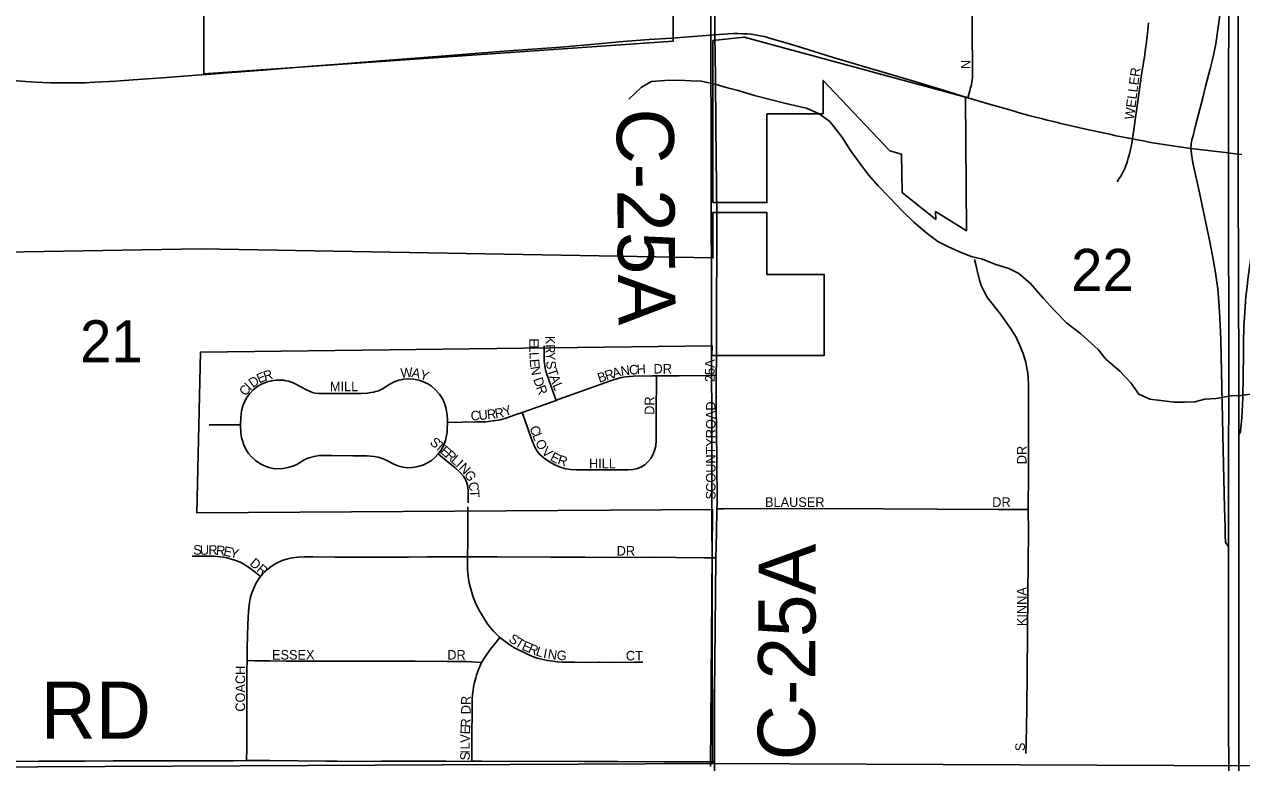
# Model space of a CAD drawing. Extents: x 0 to 680, y 0 to 440.
# Drawn here: x 477.97 to 499.3, y 223.99 to 236.91 of the extents above; entities that cross this region are included whole.
import ezdxf

# ---------------------------------------------------------------- set-up
doc = ezdxf.new("R2010")
doc.units = 0
for name, color, linetype in [('GM_X_City_Street', 7, 'Continuous'), ('GM_X_City_Street_Text', 7, 'Continuous'), ('GM_X_Corporation', 7, 'Continuous'), ('GM_X_County_Road', 7, 'Continuous'), ('GM_X_County_Road_Text', 7, 'Continuous'), ('GM_X_Interchange_Ramps', 7, 'Continuous'), ('GM_X_Interstate_Route', 7, 'Continuous'), ('GM_X_Minor_River', 7, 'Continuous'), ('GM_X_Section', 7, 'Continuous'), ('GM_X_Section_Text', 7, 'Continuous'), ('GM_X_State_Route', 7, 'Continuous'), ('GM_X_Township_Road', 7, 'Continuous'), ('GM_X_Township_Road_Text', 7, 'Continuous'), ('GM_X_Township_Subdivision', 7, 'Continuous'), ('GM_X_Township_Subdivision_Text', 7, 'Continuous')]:
    doc.layers.add(name, color=color, linetype=linetype)

msp = doc.modelspace()

# ---------------------------------------------------------------- linework, layer by layer
at = {"layer": 'GM_X_City_Street'}
for points in [[(490.07, 236.729), (490.056, 238.186), (490.049, 238.92), (490.046, 239.367), (490.045, 239.582)], [(494.5, 235.627), (494.534, 235.751), (494.547, 235.799), (494.562, 235.856), (494.57, 235.9), (494.576, 235.941), (494.579, 235.973), (494.582, 236.011), (494.583, 236.071), (494.583, 236.166), (494.573, 236.756), (494.572, 237.556), (494.572, 238.422), (494.569, 239.255)], [(497.385, 234.905), (497.466, 235.487), (497.506, 235.78), (497.544, 236.036), (497.58, 236.271), (497.598, 236.385), (497.612, 236.482), (497.628, 236.603), (497.641, 236.71), (497.651, 236.813), (497.662, 236.937)], [(497.113, 234.157), (497.145, 234.205), (497.166, 234.238), (497.188, 234.272), (497.203, 234.298), (497.22, 234.33), (497.236, 234.363), (497.253, 234.403), (497.268, 234.441), (497.282, 234.482), (497.295, 234.521), (497.31, 234.569), (497.324, 234.621), (497.343, 234.695), (497.359, 234.767), (497.372, 234.835), (497.385, 234.905)], [(490.105, 233.392), (490.105, 233.473), (490.104, 233.558)], [(495.557, 228.417), (495.561, 229.067), (495.562, 229.614), (495.562, 230.573), (495.562, 230.631), (495.552, 230.806), (495.515, 230.993), (495.471, 231.149), (495.423, 231.263), (495.343, 231.435), (495.252, 231.579), (495.091, 231.813), (494.92, 232.029), (494.846, 232.123), (494.783, 232.233), (494.732, 232.342), (494.701, 232.431), (494.662, 232.603), (494.637, 232.707), (494.616, 232.794)], [(487.286, 230.329), (487.235, 230.473), (487.117, 230.804), (487.106, 230.843), (487.096, 230.889), (487.088, 230.937), (487.081, 231.008), (487.076, 231.15), (487.076, 231.282)], [(490.093, 230.768), (490.095, 231.052)], [(486.695, 230.117), (486.739, 229.99), (486.849, 229.669), (486.917, 229.508), (486.955, 229.441), (487.003, 229.382), (487.076, 229.316), (487.157, 229.259), (487.263, 229.203), (487.374, 229.156), (487.458, 229.131), (487.544, 229.117), (487.642, 229.113), (487.993, 229.112), (488.551, 229.112), (488.638, 229.12), (488.713, 229.138), (488.784, 229.166), (488.84, 229.201), (488.896, 229.252), (488.944, 229.312), (488.982, 229.378), (489.01, 229.45), (489.032, 229.535), (489.041, 229.621), (489.042, 230.257), (489.044, 230.585), (489.045, 230.761)], [(487.286, 230.329), (487.322, 230.342), (488.239, 230.67), (488.406, 230.723), (488.503, 230.742), (488.644, 230.754), (488.972, 230.761), (489.045, 230.761)], [(489.045, 230.761), (489.443, 230.761), (489.924, 230.766), (490.093, 230.768)], [(490.106, 228.52), (490.105, 229.298), (490.09, 230.238), (490.093, 230.768)], [(485.384, 229.941), (485.384, 229.989), (485.378, 230.07), (485.374, 230.105), (485.365, 230.146), (485.361, 230.167), (485.353, 230.204), (485.342, 230.241), (485.324, 230.296), (485.302, 230.342), (485.281, 230.383), (485.243, 230.436), (485.164, 230.527), (485.107, 230.578), (485.053, 230.615), (484.963, 230.656), (484.88, 230.684), (484.784, 230.702), (484.707, 230.706), (484.62, 230.699), (484.575, 230.691), (484.534, 230.681), (484.452, 230.652), (484.374, 230.611), (484.245, 230.529), (484.175, 230.498), (484.13, 230.484), (484.091, 230.474), (484.043, 230.464), (483.983, 230.456), (483.874, 230.451), (483.567, 230.451), (483.259, 230.447), (483.13, 230.449), (483.065, 230.456), (483.023, 230.465), (482.991, 230.477), (482.902, 230.518), (482.738, 230.608), (482.717, 230.618), (482.669, 230.639), (482.648, 230.646), (482.597, 230.663), (482.556, 230.673), (482.512, 230.68), (482.453, 230.685), (482.378, 230.682), (482.302, 230.673), (482.228, 230.653), (482.127, 230.612), (482.06, 230.575), (481.983, 230.512), (481.922, 230.45), (481.897, 230.422), (481.876, 230.389), (481.828, 230.303), (481.799, 230.232), (481.778, 230.147), (481.762, 230.028), (481.758, 229.902)], [(486.695, 230.117), (487.286, 230.329)], [(485.384, 229.941), (485.89, 229.951), (486.056, 229.956), (486.192, 229.969), (486.311, 229.988), (486.426, 230.022), (486.57, 230.073), (486.695, 230.117)], [(481.213, 229.902), (481.385, 229.902), (481.639, 229.902), (481.758, 229.902)], [(481.758, 229.902), (481.757, 229.875), (481.765, 229.766), (481.772, 229.709), (481.784, 229.658), (481.798, 229.606), (481.816, 229.553), (481.847, 229.484), (481.871, 229.443), (481.9, 229.401), (481.951, 229.343), (482.023, 229.277), (482.095, 229.226), (482.182, 229.181), (482.254, 229.154), (482.329, 229.138), (482.416, 229.132), (482.504, 229.137), (482.59, 229.151), (482.674, 229.176), (482.743, 229.208), (482.884, 229.293), (482.954, 229.323), (483.049, 229.349), (483.136, 229.361), (483.365, 229.364), (483.727, 229.359), (483.978, 229.356), (484.098, 229.349), (484.173, 229.335), (484.256, 229.307), (484.335, 229.269), (484.442, 229.213), (484.533, 229.177), (484.608, 229.158), (484.684, 229.15), (484.771, 229.154), (484.868, 229.17), (484.952, 229.195), (485.022, 229.227), (485.096, 229.273), (485.164, 229.329), (485.222, 229.391)], [(485.222, 229.391), (485.224, 229.393), (485.269, 229.454), (485.302, 229.512), (485.333, 229.582), (485.35, 229.632), (485.357, 229.655), (485.363, 229.682), (485.374, 229.741), (485.378, 229.771), (485.382, 229.823), (485.384, 229.941)], [(485.746, 228.537), (485.746, 228.733), (485.74, 228.82), (485.724, 228.884), (485.698, 228.944), (485.658, 229.008), (485.608, 229.066), (485.519, 229.147), (485.3, 229.327), (485.222, 229.391)], [(490.104, 228.43), (490.222, 228.431), (491.412, 228.434), (493.022, 228.43), (493.967, 228.425), (495.037, 228.42), (495.438, 228.418), (495.557, 228.417)], [(495.516, 224.146), (495.519, 224.32), (495.533, 224.931), (495.539, 225.569), (495.543, 226.225), (495.552, 226.964), (495.559, 228.026), (495.557, 228.417)], [(489.935, 216.438), (489.935, 216.438), (489.948, 217.062), (489.958, 217.746), (489.978, 218.906), (489.99, 219.727), (490.003, 220.472), (490.013, 221.304), (490.029, 222.212), (490.05, 223.274), (490.063, 224.001)]]:
    msp.add_lwpolyline(points, dxfattribs=at)
at = {"layer": 'GM_X_Corporation'}
msp.add_lwpolyline([(489.993, 223.916), (490.028, 228.417), (480.996, 228.36), (481.058, 231.171), (490.018, 231.285), (490.014, 231.113), (491.984, 231.115), (491.982, 232.533), (490.981, 232.533), (490.98, 233.618), (490.033, 233.617), (490.033, 232.823), (481.065, 232.983), (474.871, 232.875), (474.871, 236.22), (473.725, 236.49), (472.735, 236.905), (472.245, 237.111), (472.245, 241.651), (481.118, 241.691), (481.055, 250.48)], dxfattribs=at)
for points in [[(481.118, 241.691), (481.118, 236.046), (489.339, 236.618), (489.339, 237.172), (490.014, 237.16), (489.995, 239.503), (489.988, 239.503), (488.871, 239.486), (488.876, 240.02), (489.982, 240.037), (489.974, 240.431), (488.863, 240.392), (488.848, 242.067), (488.839, 242.461), (487.667, 242.441), (487.676, 241.828), (484.131, 241.754)], [(490.033, 236.632), (490.033, 233.791), (490.981, 233.791), (490.979, 235.345), (491.967, 235.346), (491.966, 235.93), (493.135, 234.7), (493.338, 234.64), (493.347, 233.969), (493.937, 233.498), (493.933, 233.633), (494.473, 233.299), (494.461, 235.639), (490.58, 236.685)]]:
    msp.add_lwpolyline(points, close=True, dxfattribs=at)
at = {"layer": 'GM_X_County_Road'}
for points in [[(490.104, 233.558), (490.085, 235.118), (490.081, 235.986), (490.07, 236.729)], [(490.103, 233.025), (490.104, 233.195), (490.105, 233.391), (490.105, 233.392)], [(490.095, 231.387), (490.097, 231.934), (490.103, 233.021), (490.103, 233.025)], [(490.095, 231.052), (490.098, 231.228), (490.095, 231.387)], [(490.085, 227.574), (490.097, 228.006), (490.104, 228.43)], [(490.104, 228.43), (490.106, 228.52)], [(490.063, 224.001), (490.063, 225.229), (490.074, 226.342), (490.085, 227.574)]]:
    msp.add_lwpolyline(points, dxfattribs=at)
at = {"layer": 'GM_X_Interchange_Ramps'}
for points in [[(499.069, 239.688), (499.034, 239.608), (499.013, 239.56), (499.007, 239.514), (499.005, 239.374), (499.004, 239.346), (498.988, 238.283), (498.982, 237.965), (498.974, 237.801), (498.951, 237.463), (498.917, 237.114), (498.881, 236.82), (498.841, 236.572), (498.796, 236.346), (498.745, 236.133), (498.663, 235.826), (498.618, 235.628), (498.484, 235.117), (498.444, 234.963), (498.425, 234.89), (498.413, 234.823), (498.406, 234.74)], [(498.406, 234.74), (498.422, 234.604), (498.441, 234.49), (498.55, 233.993), (498.739, 233.103), (498.81, 232.738), (498.845, 232.521), (498.876, 232.282), (498.898, 232.053), (498.915, 231.78), (498.93, 231.385), (498.97, 229.464), (498.995, 228.45), (499.004, 228.115), (499.007, 227.939), (499.011, 227.876), (499.013, 227.851), (499.026, 227.821), (499.045, 227.792), (499.066, 227.763)], [(499.245, 229.732), (499.265, 229.755), (499.273, 229.776), (499.277, 229.801), (499.288, 229.904), (499.299, 230.021), (499.314, 230.372), (499.325, 231.139), (499.328, 231.347), (499.336, 231.61), (499.349, 231.873), (499.371, 232.146), (499.39, 232.323), (499.41, 232.494), (499.456, 232.82), (499.561, 233.47), (499.609, 233.77), (499.662, 234.115), (499.726, 234.469), (499.742, 234.589)]]:
    msp.add_lwpolyline(points, dxfattribs=at)
at = {"layer": 'GM_X_Interstate_Route'}
for points in [[(499.074, 221.303), (499.067, 225.241), (499.066, 227.763), (499.065, 229.04), (499.069, 230.749), (499.063, 234.252), (499.064, 234.66), (499.068, 235.598), (499.07, 237.416), (499.069, 239.688), (499.068, 241.014), (499.057, 245.417), (499.021, 246.364)], [(499.251, 215.048), (499.251, 215.074), (499.251, 217.418), (499.248, 220.255), (499.248, 224.759), (499.245, 229.732), (499.245, 230.699), (499.235, 234.233), (499.236, 234.641), (499.237, 236.207), (499.231, 238.398), (499.236, 241.137), (499.239, 243.03), (499.243, 244.793), (499.238, 245.307), (499.227, 245.734), (499.207, 246.182), (499.197, 246.357)]]:
    msp.add_lwpolyline(points, dxfattribs=at)
at = {"layer": 'GM_X_Minor_River'}
for points in [[(491.672, 235.443), (491.465, 235.493), (491.285, 235.535), (491.058, 235.592), (490.765, 235.669), (490.479, 235.753), (490.266, 235.809), (490.073, 235.865), (489.826, 235.915), (489.652, 235.924), (489.439, 235.933), (489.191, 235.929), (488.957, 235.912), (488.782, 235.814), (488.559, 235.603)], [(499.545, 230.447), (499.284, 230.417), (499.11, 230.406), (498.849, 230.362), (498.648, 230.351), (498.474, 230.306), (498.293, 230.295), (498.113, 230.298), (497.926, 230.32), (497.686, 230.35), (497.493, 230.439), (497.355, 230.635), (497.164, 230.838), (496.919, 231.048), (496.781, 231.217), (496.477, 231.496), (496.225, 231.686), (496.014, 231.91), (495.816, 232.12), (495.598, 232.377), (495.393, 232.553), (495.22, 232.636), (494.974, 232.712), (494.754, 232.802), (494.555, 232.845), (494.342, 232.934), (494.162, 233.017), (493.976, 233.113), (493.784, 233.249), (493.553, 233.446), (493.354, 233.642), (493.13, 233.88), (492.925, 234.089), (492.76, 234.279), (492.603, 234.488), (492.445, 234.704), (492.294, 234.94), (492.083, 235.211), (491.898, 235.347), (491.672, 235.443)]]:
    msp.add_lwpolyline(points, dxfattribs=at)
at = {"layer": 'GM_X_Section'}
msp.add_lwpolyline([(472.268, 225.115), (472.319, 241.773), (489.987, 242.13), (490.027, 223.974), (473.467, 223.892)], dxfattribs=at)
msp.add_lwpolyline([(507.628, 241.733), (507.54, 223.893), (490.027, 223.974), (489.987, 242.13), (499.118, 242.119)], close=True, dxfattribs=at)
at = {"layer": 'GM_X_State_Route'}
for points in [[(489.315, 236.671), (489.613, 236.691), (489.842, 236.71)], [(489.842, 236.71), (490.07, 236.729)], [(490.07, 236.729), (490.295, 236.748), (490.397, 236.752), (490.479, 236.752), (490.559, 236.749), (490.634, 236.745), (490.701, 236.74), (490.772, 236.731), (490.831, 236.719), (490.895, 236.706), (490.93, 236.697)], [(490.93, 236.697), (490.974, 236.686), (491.085, 236.655), (491.229, 236.612), (491.413, 236.557), (491.619, 236.493), (491.899, 236.407), (492.139, 236.334), (492.377, 236.263), (492.656, 236.18), (492.977, 236.085), (493.569, 235.909), (494.169, 235.728), (494.5, 235.627)], [(481.162, 236.035), (481.532, 236.062), (482.074, 236.105), (483.008, 236.178), (483.48, 236.215), (484.29, 236.281), (485.272, 236.357), (486.379, 236.441), (487.37, 236.515), (488.031, 236.573), (488.384, 236.604), (488.917, 236.646), (489.315, 236.671)], [(477.074, 235.976), (478.169, 235.901), (478.43, 235.889), (478.666, 235.887), (478.804, 235.887), (478.924, 235.888), (479.039, 235.891), (479.207, 235.898), (479.343, 235.904), (479.576, 235.92), (479.877, 235.94), (480.387, 235.978), (480.913, 236.017), (480.986, 236.022)], [(480.986, 236.022), (481.162, 236.035)], [(494.5, 235.627), (494.899, 235.508), (495.127, 235.442), (495.27, 235.401), (495.419, 235.359), (495.57, 235.319), (495.687, 235.288), (495.79, 235.262), (495.889, 235.237), (495.999, 235.21), (496.044, 235.199)], [(496.044, 235.199), (496.129, 235.178), (496.255, 235.148), (496.438, 235.106), (496.617, 235.065), (496.816, 235.022), (497.007, 234.981), (497.092, 234.963)], [(497.092, 234.963), (497.159, 234.949), (497.29, 234.923), (497.385, 234.905), (497.436, 234.895), (497.568, 234.871), (497.704, 234.846), (497.815, 234.827), (498.011, 234.796), (498.406, 234.74), (498.602, 234.714), (498.858, 234.684), (499.064, 234.66), (499.095, 234.656), (499.236, 234.641), (499.299, 234.635)]]:
    msp.add_lwpolyline(points, dxfattribs=at)
at = {"layer": 'GM_X_Township_Road'}
for points in [[(474.934, 224.01), (476.17, 224.013), (476.576, 224.009), (477.416, 224.01), (477.668, 224.008), (478.226, 224.01), (478.599, 224.011), (479.026, 224.013), (479.53, 224.016), (480.066, 224.018), (480.548, 224.019), (481.565, 224.017), (481.638, 224.018), (481.862, 224.022)], [(481.862, 224.022), (482.272, 224.021), (483.256, 224.013), (483.453, 224.01), (483.902, 224.007), (484.23, 224.011), (484.394, 224.011), (484.709, 224.013), (485.046, 224.012), (485.353, 224.011), (485.583, 224.009), (485.809, 224.014)], [(485.809, 224.014), (485.986, 224.01), (487.779, 224.008)], [(487.779, 224.008), (487.911, 224.009), (488.37, 224.005), (489.179, 223.999), (489.617, 223.999), (490.063, 224.001)]]:
    msp.add_lwpolyline(points, dxfattribs=at)
at = {"layer": 'GM_X_Township_Subdivision'}
for points in [[(485.744, 228.465), (485.744, 228.238), (485.743, 227.877), (485.737, 227.592)], [(480.915, 227.6), (481.042, 227.599), (481.295, 227.6), (481.404, 227.592), (481.458, 227.584), (481.522, 227.571), (481.66, 227.533), (481.751, 227.497), (481.829, 227.456), (481.938, 227.382), (482.015, 227.321), (482.112, 227.245)], [(482.112, 227.245), (482.145, 227.286), (482.216, 227.356), (482.295, 227.418), (482.39, 227.476), (482.491, 227.524), (482.586, 227.557), (482.662, 227.574), (482.765, 227.585), (482.878, 227.59), (483.025, 227.588), (483.415, 227.585), (483.6, 227.586), (484.038, 227.583), (484.333, 227.585), (484.704, 227.584), (485.032, 227.587), (485.737, 227.592)], [(485.737, 227.592), (485.736, 227.528), (485.737, 227.428), (485.738, 227.373), (485.743, 227.296), (485.746, 227.258), (485.753, 227.201), (485.767, 227.137), (485.787, 227.048), (485.822, 226.923), (485.845, 226.853), (485.876, 226.783), (485.936, 226.659), (486.013, 226.528), (486.091, 226.407), (486.188, 226.29), (486.272, 226.206), (486.303, 226.176)], [(485.737, 227.592), (485.82, 227.592), (486.254, 227.587), (487.193, 227.586), (487.795, 227.582), (488.266, 227.579), (488.901, 227.582), (489.887, 227.575), (490.085, 227.574)], [(481.873, 225.773), (481.876, 225.996), (481.89, 226.41), (481.899, 226.63), (481.915, 226.789), (481.929, 226.862), (481.951, 226.942), (481.991, 227.043), (482.03, 227.124), (482.082, 227.207), (482.112, 227.245)], [(485.982, 225.741), (486.032, 225.822), (486.132, 225.965), (486.212, 226.067), (486.303, 226.176)], [(486.303, 226.176), (486.371, 226.122), (486.461, 226.06), (486.546, 226.005), (486.579, 225.987), (486.706, 225.925), (486.799, 225.879), (486.875, 225.846), (486.955, 225.815), (487.059, 225.79), (487.139, 225.775), (487.231, 225.762), (487.31, 225.752), (487.393, 225.748), (487.467, 225.747), (487.611, 225.746), (487.884, 225.741), (488.037, 225.745), (488.048, 225.748), (488.222, 225.742), (488.671, 225.744), (488.808, 225.744)], [(481.862, 224.022), (481.868, 224.233), (481.87, 225.602), (481.873, 225.773)], [(481.873, 225.773), (482.005, 225.771), (482.279, 225.766), (482.564, 225.765), (484.152, 225.762), (484.821, 225.761), (485.38, 225.757), (485.715, 225.757), (485.982, 225.741)], [(485.809, 224.014), (485.81, 224.121), (485.813, 224.461), (485.815, 224.887), (485.816, 225.007), (485.817, 225.084), (485.825, 225.183), (485.833, 225.251), (485.841, 225.315), (485.856, 225.392), (485.88, 225.469), (485.895, 225.52), (485.918, 225.587), (485.982, 225.741)]]:
    msp.add_lwpolyline(points, dxfattribs=at)

# ---------------------------------------------------------------- texts
at = {"layer": 'GM_X_City_Street_Text'}
for s, height, rotation, p in [('N', 0.167, 90, (494.544, 236.128)), ('WELLER', 0.1669, 82.7469, (497.408, 235.236)), ('E', 0.167, 270.0547, (486.817, 231.414)), ('K', 0.167, 270.2405, (487.101, 231.458)), ('L', 0.167, 270.502, (486.817, 231.295)), ('L', 0.167, 272.6217, (486.819, 231.171)), ('R', 0.167, 270.2429, (487.102, 231.311)), ('Y', 0.167, 273.0711, (487.103, 231.17)), ('E', 0.167, 274.1816, (486.824, 231.048)), ('N', 0.167, 280.3218, (486.835, 230.912)), ('S', 0.167, 275.833, (487.111, 231.014)), ('N', 0.167, 8.1796, (488.429, 230.755)), ('C', 0.167, 5.1307, (488.572, 230.775)), ('H', 0.167, 3.5204, (488.703, 230.787)), ('DR', 0.1669, 0, (488.994, 230.799)), ('25A', 0.1669, 90, (490.064, 230.65)), ('D', 0.167, 35.8426, (481.975, 230.542)), ('E', 0.167, 23.6435, (482.086, 230.623)), ('R', 0.167, 16.8528, (482.188, 230.668)), ('W', 0.167, 4.0557, (484.568, 230.725)), ('A', 0.167, 347.9785, (484.746, 230.74)), ('Y', 0.167, 341.9797, (484.885, 230.71)), ('D', 0.167, 289.5067, (486.883, 230.698)), ('T', 0.167, 287.5986, (487.131, 230.861)), ('A', 0.167, 289.9884, (487.169, 230.742)), ('B', 0.167, 17.8205, (488.043, 230.636)), ('R', 0.167, 17.7974, (488.169, 230.676)), ('A', 0.167, 15.6692, (488.294, 230.716)), ('C', 0.167, 53.3049, (481.853, 230.393)), ('I', 0.167, 44.9072, (481.928, 230.494)), ('MILL', 0.1669, 0, (483.325, 230.49)), ('R', 0.167, 290.0853, (486.933, 230.558)), ('L', 0.167, 291.811, (487.221, 230.598)), ('DR', 0.1669, 90, (489.006, 230.077)), ('ROAD', 0.1669, 90, (490.079, 229.666)), ('C', 0.167, 2.1615, (485.794, 229.977)), ('U', 0.167, 5.7664, (485.937, 229.982)), ('R', 0.167, 6.4352, (486.086, 229.997)), ('R', 0.167, 9.1964, (486.226, 230.013)), ('Y', 0.167, 21.0649, (486.392, 230.044)), ('C', 0.167, 288.9496, (486.821, 229.852)), ('S', 0.167, 319.7187, (485.063, 229.573)), ('L', 0.167, 291.7162, (486.867, 229.719)), ('COUNTY', 0.1669, 90, (490.079, 228.726)), ('T', 0.167, 319.6802, (485.153, 229.497)), ('E', 0.167, 319.7075, (485.243, 229.42)), ('R', 0.167, 319.7095, (485.332, 229.345)), ('O', 0.167, 296.4188, (486.916, 229.596)), ('V', 0.167, 317.6304, (487.022, 229.411)), ('DR', 0.1669, 90, (495.527, 229.211)), ('L', 0.167, 319.6898, (485.433, 229.259)), ('I', 0.167, 316.5148, (485.521, 229.185)), ('N', 0.167, 314.9227, (485.573, 229.135)), ('E', 0.167, 332.3455, (487.169, 229.285)), ('R', 0.167, 341.8909, (487.301, 229.219)), ('HILL', 0.1669, 0, (487.863, 229.139)), ('G', 0.167, 301.1737, (485.67, 229.039)), ('C', 0.167, 280.281, (485.75, 228.886)), ('T', 0.167, 272.7328, (485.773, 228.761)), ('S', 0.167, 90, (490.079, 228.594)), ('BLAUSER', 0.1669, 0, (490.947, 228.464)), ('DR', 0.1669, 0, (494.927, 228.464)), ('KINNA', 0.1669, 90, (495.527, 226.376)), ('S', 0.167, 90, (495.498, 224.188))]:
    msp.add_text(s, height=height, rotation=rotation, dxfattribs=at).set_placement(p)
at = {"layer": 'GM_X_County_Road_Text'}
for rotation, p in [(270.548, (488.345, 235.435)), (89.748, (491.82, 224.025))]:
    msp.add_text('C-25A', height=1.0014, rotation=rotation, dxfattribs=at).set_placement(p)
at = {"layer": 'GM_X_Section_Text'}
for s, p in [('22', (496.308, 232.243)), ('21', (478.948, 230.994))]:
    msp.add_text(s, height=0.7377, rotation=0, dxfattribs=at).set_placement(p)
at = {"layer": 'GM_X_Township_Road_Text'}
msp.add_text('RD', height=1.0014, rotation=0, dxfattribs=at).set_placement((478.258, 224.405))
at = {"layer": 'GM_X_Township_Subdivision_Text'}
for s, height, rotation, p in [('S', 0.167, 359.8907, (480.931, 227.627)), ('U', 0.167, 359.8907, (481.048, 227.626)), ('R', 0.167, 359.8786, (481.195, 227.626)), ('R', 0.167, 354.038, (481.323, 227.626)), ('E', 0.167, 348.9793, (481.45, 227.613)), ('Y', 0.167, 345.6881, (481.563, 227.591)), ('DR', 0.1669, 0, (488.348, 227.612)), ('DR', 0.1669, 319.0784, (481.907, 227.457)), ('S', 0.167, 323.2175, (486.443, 226.122)), ('T', 0.167, 329.0958, (486.552, 226.041)), ('E', 0.167, 336.1503, (486.673, 225.971)), ('R', 0.167, 337.7323, (486.785, 225.921)), ('ESSEX', 0.1669, 0, (482.311, 225.791)), ('DR', 0.1669, 0, (485.381, 225.791)), ('L', 0.167, 341.6997, (486.919, 225.867)), ('I', 0.167, 348.8454, (487.053, 225.824)), ('N', 0.167, 351.6588, (487.133, 225.808)), ('G', 0.167, 356.6824, (487.295, 225.786)), ('CT', 0.1669, 0, (488.509, 225.776)), ('COACH', 0.1669, 90, (481.839, 224.878)), ('DR', 0.1669, 90, (485.79, 224.834)), ('R', 0.167, 87.1813, (485.782, 224.597)), ('E', 0.167, 87.5947, (485.777, 224.48)), ('V', 0.167, 89.4098, (485.776, 224.334)), ('L', 0.167, 89.9572, (485.776, 224.217)), ('S', 0.167, 89.9727, (485.775, 224.026)), ('I', 0.167, 89.9563, (485.775, 224.144))]:
    msp.add_text(s, height=height, rotation=rotation, dxfattribs=at).set_placement(p)

doc.saveas('drawing.dxf')
